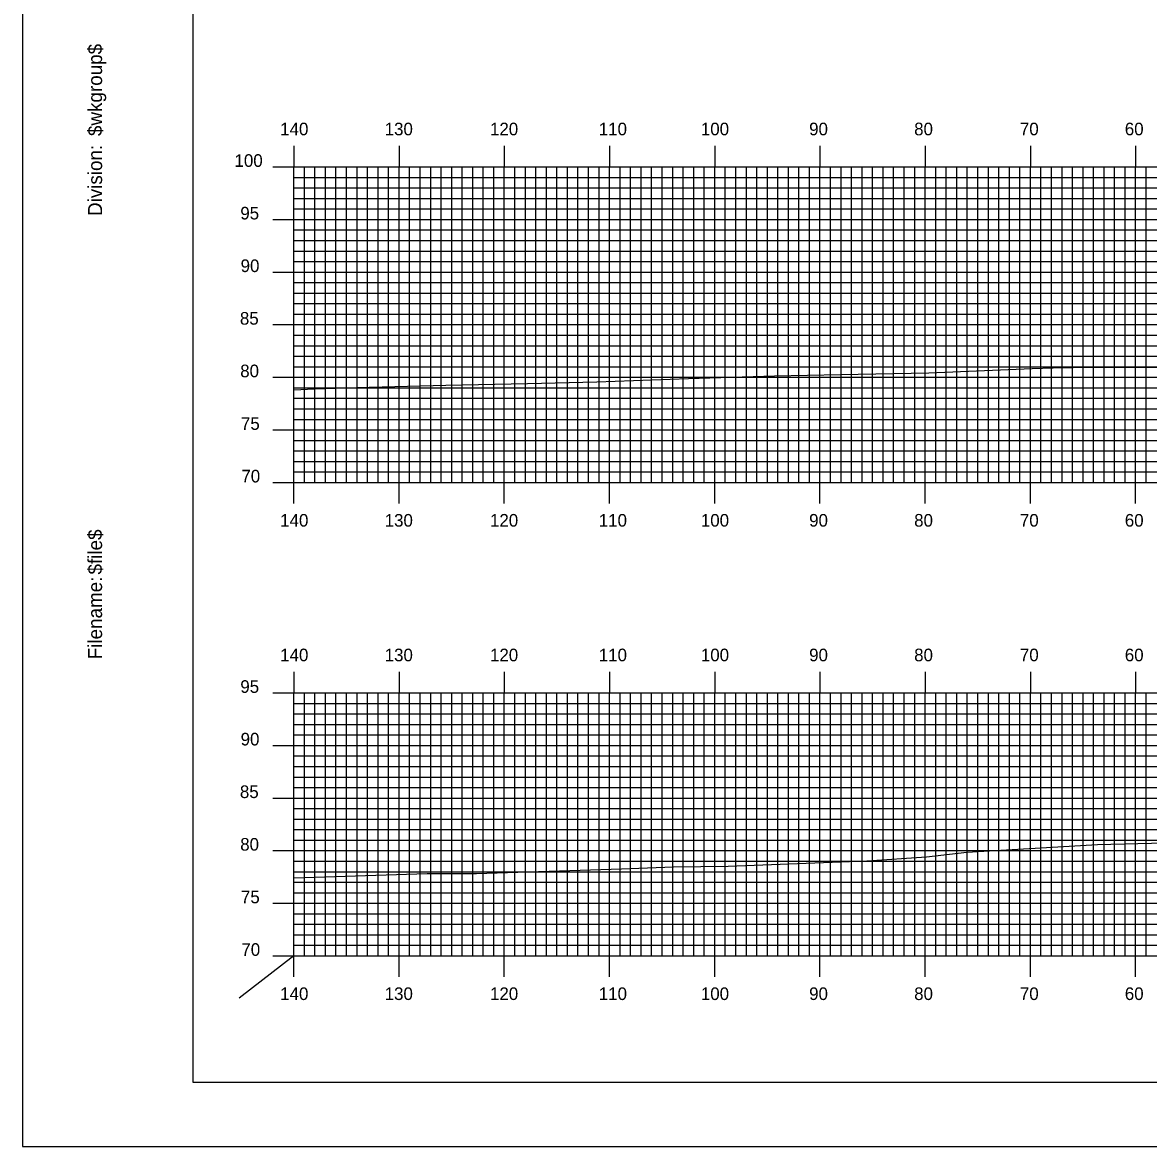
# Model space of a CAD drawing. Extents: x 1777531 to 1777875, y 442591 to 442811.
# Drawn here: x 1777531.5 to 1777638.5, y 442590.5 to 442697.4 of the extents above; entities that cross this region are included whole.
import ezdxf

# ---------------------------------------------------------------- set-up
doc = ezdxf.new("R2010")
doc.units = 0
for name, color, linetype in [('BORDER', 7, 'Continuous'), ('H_V ANNOTATION', 7, 'Continuous'), ('MAJOR', 7, 'Continuous'), ('MINOR', 7, 'Continuous'), ('PLOT BOUNDARY', 7, 'Continuous'), ('S_Roadway_Centerline', 7, 'Continuous')]:
    doc.layers.add(name, color=color, linetype=linetype)

msp = doc.modelspace()

# ---------------------------------------------------------------- linework, layer by layer
at = {"layer": 'BORDER'}
msp.add_lwpolyline([(1777547.68, 442596.67), (1777867.68, 442596.67), (1777867.68, 442806.67), (1777547.68, 442806.67)], close=True, dxfattribs=at)
at = {"layer": 'MAJOR'}
for p, q in [((1777557.28, 442685.67), (1777557.28, 442683.67)), ((1777567.28, 442685.67), (1777567.28, 442683.67)), ((1777577.28, 442685.67), (1777577.28, 442683.67)), ((1777587.28, 442685.67), (1777587.28, 442683.67)), ((1777597.28, 442685.67), (1777597.28, 442683.67)), ((1777607.28, 442685.67), (1777607.28, 442683.67)), ((1777617.28, 442685.67), (1777617.28, 442683.67)), ((1777627.28, 442685.67), (1777627.28, 442683.67)), ((1777637.28, 442685.67), (1777637.28, 442683.67)), ((1777555.27, 442683.67), (1777557.28, 442683.67)), ((1777557.28, 442683.67), (1777837.28, 442683.67)), ((1777557.28, 442653.67), (1777557.28, 442683.67)), ((1777557.28, 442653.67), (1777557.28, 442683.67)), ((1777557.28, 442683.67), (1777837.28, 442683.67)), ((1777567.28, 442653.67), (1777567.28, 442683.67)), ((1777577.28, 442653.67), (1777577.28, 442683.67)), ((1777587.28, 442653.67), (1777587.28, 442683.67)), ((1777597.28, 442653.67), (1777597.28, 442683.67)), ((1777607.28, 442653.67), (1777607.28, 442683.67)), ((1777617.28, 442653.67), (1777617.28, 442683.67)), ((1777627.28, 442653.67), (1777627.28, 442683.67)), ((1777637.28, 442653.67), (1777637.28, 442683.67)), ((1777555.27, 442678.67), (1777557.28, 442678.67)), ((1777557.28, 442678.67), (1777837.28, 442678.67)), ((1777555.27, 442673.67), (1777557.28, 442673.67)), ((1777557.28, 442673.67), (1777837.28, 442673.67)), ((1777555.27, 442668.67), (1777557.28, 442668.67)), ((1777557.28, 442668.67), (1777837.28, 442668.67)), ((1777555.27, 442663.67), (1777557.28, 442663.67)), ((1777557.28, 442663.67), (1777837.28, 442663.67)), ((1777555.27, 442658.67), (1777557.28, 442658.67)), ((1777557.28, 442658.67), (1777837.28, 442658.67)), ((1777555.27, 442653.67), (1777557.28, 442653.67)), ((1777557.28, 442653.67), (1777837.28, 442653.67)), ((1777557.28, 442653.67), (1777837.28, 442653.67)), ((1777557.28, 442651.66), (1777557.28, 442653.67)), ((1777567.28, 442651.66), (1777567.28, 442653.67)), ((1777577.28, 442651.66), (1777577.28, 442653.67)), ((1777587.28, 442651.66), (1777587.28, 442653.67)), ((1777597.28, 442651.66), (1777597.28, 442653.67)), ((1777607.28, 442651.66), (1777607.28, 442653.67)), ((1777617.28, 442651.66), (1777617.28, 442653.67)), ((1777627.28, 442651.66), (1777627.28, 442653.67)), ((1777637.28, 442651.66), (1777637.28, 442653.67)), ((1777557.28, 442635.67), (1777557.28, 442633.67)), ((1777567.28, 442635.67), (1777567.28, 442633.67)), ((1777577.28, 442635.67), (1777577.28, 442633.67)), ((1777587.28, 442635.67), (1777587.28, 442633.67)), ((1777597.28, 442635.67), (1777597.28, 442633.67)), ((1777607.28, 442635.67), (1777607.28, 442633.67)), ((1777617.28, 442635.67), (1777617.28, 442633.67)), ((1777627.28, 442635.67), (1777627.28, 442633.67)), ((1777637.28, 442635.67), (1777637.28, 442633.67)), ((1777555.27, 442633.67), (1777557.28, 442633.67)), ((1777557.28, 442633.67), (1777837.28, 442633.67)), ((1777557.28, 442608.67), (1777557.28, 442633.67)), ((1777557.28, 442608.67), (1777557.28, 442633.67)), ((1777557.28, 442633.67), (1777837.28, 442633.67)), ((1777567.28, 442608.67), (1777567.28, 442633.67)), ((1777577.28, 442608.67), (1777577.28, 442633.67)), ((1777587.28, 442608.67), (1777587.28, 442633.67)), ((1777597.28, 442608.67), (1777597.28, 442633.67)), ((1777607.28, 442608.67), (1777607.28, 442633.67)), ((1777617.28, 442608.67), (1777617.28, 442633.67)), ((1777627.28, 442608.67), (1777627.28, 442633.67)), ((1777637.28, 442608.67), (1777637.28, 442633.67)), ((1777555.27, 442628.67), (1777557.28, 442628.67)), ((1777557.28, 442628.67), (1777837.28, 442628.67)), ((1777555.27, 442623.67), (1777557.28, 442623.67)), ((1777557.28, 442623.67), (1777837.28, 442623.67)), ((1777555.27, 442618.67), (1777557.28, 442618.67)), ((1777557.28, 442618.67), (1777837.28, 442618.67)), ((1777555.27, 442613.67), (1777557.28, 442613.67)), ((1777557.28, 442613.67), (1777837.28, 442613.67)), ((1777557.28, 442608.67), (1777552.09, 442604.64)), ((1777555.27, 442608.67), (1777557.28, 442608.67)), ((1777557.28, 442608.67), (1777837.28, 442608.67)), ((1777557.28, 442608.67), (1777837.28, 442608.67)), ((1777557.28, 442606.66), (1777557.28, 442608.67)), ((1777567.28, 442606.66), (1777567.28, 442608.67)), ((1777577.28, 442606.66), (1777577.28, 442608.67)), ((1777587.28, 442606.66), (1777587.28, 442608.67)), ((1777597.28, 442606.66), (1777597.28, 442608.67)), ((1777607.28, 442606.66), (1777607.28, 442608.67)), ((1777617.28, 442606.66), (1777617.28, 442608.67)), ((1777627.28, 442606.66), (1777627.28, 442608.67)), ((1777637.28, 442606.66), (1777637.28, 442608.67))]:
    msp.add_line(p, q, dxfattribs=at)
at = {"layer": 'MINOR'}
for p, q in [((1777558.28, 442653.67), (1777558.28, 442683.67)), ((1777559.28, 442653.67), (1777559.28, 442683.67)), ((1777560.28, 442653.67), (1777560.28, 442683.67)), ((1777561.28, 442653.67), (1777561.28, 442683.67)), ((1777562.28, 442653.67), (1777562.28, 442683.67)), ((1777563.28, 442653.67), (1777563.28, 442683.67)), ((1777564.28, 442653.67), (1777564.28, 442683.67)), ((1777565.28, 442653.67), (1777565.28, 442683.67)), ((1777566.28, 442653.67), (1777566.28, 442683.67)), ((1777568.28, 442653.67), (1777568.28, 442683.67)), ((1777569.28, 442653.67), (1777569.28, 442683.67)), ((1777570.28, 442653.67), (1777570.28, 442683.67)), ((1777571.28, 442653.67), (1777571.28, 442683.67)), ((1777572.28, 442653.67), (1777572.28, 442683.67)), ((1777573.28, 442653.67), (1777573.28, 442683.67)), ((1777574.28, 442653.67), (1777574.28, 442683.67)), ((1777575.28, 442653.67), (1777575.28, 442683.67)), ((1777576.28, 442653.67), (1777576.28, 442683.67)), ((1777578.28, 442653.67), (1777578.28, 442683.67)), ((1777579.28, 442653.67), (1777579.28, 442683.67)), ((1777580.28, 442653.67), (1777580.28, 442683.67)), ((1777581.28, 442653.67), (1777581.28, 442683.67)), ((1777582.28, 442653.67), (1777582.28, 442683.67)), ((1777583.28, 442653.67), (1777583.28, 442683.67)), ((1777584.28, 442653.67), (1777584.28, 442683.67)), ((1777585.28, 442653.67), (1777585.28, 442683.67)), ((1777586.28, 442653.67), (1777586.28, 442683.67)), ((1777588.28, 442653.67), (1777588.28, 442683.67)), ((1777589.28, 442653.67), (1777589.28, 442683.67)), ((1777590.28, 442653.67), (1777590.28, 442683.67)), ((1777591.28, 442653.67), (1777591.28, 442683.67)), ((1777592.28, 442653.67), (1777592.28, 442683.67)), ((1777593.28, 442653.67), (1777593.28, 442683.67)), ((1777594.28, 442653.67), (1777594.28, 442683.67)), ((1777595.28, 442653.67), (1777595.28, 442683.67)), ((1777596.28, 442653.67), (1777596.28, 442683.67)), ((1777598.28, 442653.67), (1777598.28, 442683.67)), ((1777599.28, 442653.67), (1777599.28, 442683.67)), ((1777600.28, 442653.67), (1777600.28, 442683.67)), ((1777601.28, 442653.67), (1777601.28, 442683.67)), ((1777602.28, 442653.67), (1777602.28, 442683.67)), ((1777603.28, 442653.67), (1777603.28, 442683.67)), ((1777604.28, 442653.67), (1777604.28, 442683.67)), ((1777605.28, 442653.67), (1777605.28, 442683.67)), ((1777606.28, 442653.67), (1777606.28, 442683.67)), ((1777608.28, 442653.67), (1777608.28, 442683.67)), ((1777609.28, 442653.67), (1777609.28, 442683.67)), ((1777610.28, 442653.67), (1777610.28, 442683.67)), ((1777611.28, 442653.67), (1777611.28, 442683.67)), ((1777612.28, 442653.67), (1777612.28, 442683.67)), ((1777613.28, 442653.67), (1777613.28, 442683.67)), ((1777614.28, 442653.67), (1777614.28, 442683.67)), ((1777615.28, 442653.67), (1777615.28, 442683.67)), ((1777616.28, 442653.67), (1777616.28, 442683.67)), ((1777618.28, 442653.67), (1777618.28, 442683.67)), ((1777619.28, 442653.67), (1777619.28, 442683.67)), ((1777620.28, 442653.67), (1777620.28, 442683.67)), ((1777621.28, 442653.67), (1777621.28, 442683.67)), ((1777622.28, 442653.67), (1777622.28, 442683.67)), ((1777623.28, 442653.67), (1777623.28, 442683.67)), ((1777624.28, 442653.67), (1777624.28, 442683.67)), ((1777625.28, 442653.67), (1777625.28, 442683.67)), ((1777626.28, 442653.67), (1777626.28, 442683.67)), ((1777628.28, 442653.67), (1777628.28, 442683.67)), ((1777629.28, 442653.67), (1777629.28, 442683.67)), ((1777630.28, 442653.67), (1777630.28, 442683.67)), ((1777631.28, 442653.67), (1777631.28, 442683.67)), ((1777632.28, 442653.67), (1777632.28, 442683.67)), ((1777633.28, 442653.67), (1777633.28, 442683.67)), ((1777634.28, 442653.67), (1777634.28, 442683.67)), ((1777635.28, 442653.67), (1777635.28, 442683.67)), ((1777636.28, 442653.67), (1777636.28, 442683.67)), ((1777638.28, 442653.67), (1777638.28, 442683.67)), ((1777557.28, 442682.67), (1777837.28, 442682.67)), ((1777557.28, 442682.67), (1777559.28, 442682.67)), ((1777557.28, 442681.67), (1777837.28, 442681.67)), ((1777557.28, 442681.67), (1777559.28, 442681.67)), ((1777557.28, 442680.67), (1777837.28, 442680.67)), ((1777557.28, 442680.67), (1777559.28, 442680.67)), ((1777557.28, 442679.67), (1777837.28, 442679.67)), ((1777557.28, 442679.67), (1777559.28, 442679.67)), ((1777557.28, 442677.67), (1777837.28, 442677.67)), ((1777557.28, 442677.67), (1777559.28, 442677.67)), ((1777557.28, 442676.67), (1777837.28, 442676.67)), ((1777557.28, 442676.67), (1777559.28, 442676.67)), ((1777557.28, 442675.67), (1777837.28, 442675.67)), ((1777557.28, 442675.67), (1777559.28, 442675.67)), ((1777557.28, 442674.67), (1777837.28, 442674.67)), ((1777557.28, 442674.67), (1777559.28, 442674.67)), ((1777557.28, 442672.67), (1777837.28, 442672.67)), ((1777557.28, 442672.67), (1777559.28, 442672.67)), ((1777557.28, 442671.67), (1777837.28, 442671.67)), ((1777557.28, 442671.67), (1777559.28, 442671.67)), ((1777557.28, 442670.67), (1777837.28, 442670.67)), ((1777557.28, 442670.67), (1777559.28, 442670.67)), ((1777557.28, 442669.67), (1777837.28, 442669.67)), ((1777557.28, 442669.67), (1777559.28, 442669.67)), ((1777557.28, 442667.67), (1777837.28, 442667.67)), ((1777557.28, 442667.67), (1777559.28, 442667.67)), ((1777557.28, 442666.67), (1777837.28, 442666.67)), ((1777557.28, 442666.67), (1777559.28, 442666.67)), ((1777557.28, 442665.67), (1777837.28, 442665.67)), ((1777557.28, 442665.67), (1777559.28, 442665.67)), ((1777557.28, 442664.67), (1777837.28, 442664.67)), ((1777557.28, 442664.67), (1777559.28, 442664.67)), ((1777557.28, 442662.67), (1777837.28, 442662.67)), ((1777557.28, 442662.67), (1777559.28, 442662.67)), ((1777557.28, 442661.67), (1777837.28, 442661.67)), ((1777557.28, 442661.67), (1777559.28, 442661.67)), ((1777557.28, 442660.67), (1777837.28, 442660.67)), ((1777557.28, 442660.67), (1777559.28, 442660.67)), ((1777557.28, 442659.67), (1777837.28, 442659.67)), ((1777557.28, 442659.67), (1777559.28, 442659.67)), ((1777557.28, 442657.67), (1777837.28, 442657.67)), ((1777557.28, 442657.67), (1777559.28, 442657.67)), ((1777557.28, 442656.67), (1777837.28, 442656.67)), ((1777557.28, 442656.67), (1777559.28, 442656.67)), ((1777557.28, 442655.67), (1777837.28, 442655.67)), ((1777557.28, 442655.67), (1777559.28, 442655.67)), ((1777557.28, 442654.67), (1777837.28, 442654.67)), ((1777557.28, 442654.67), (1777559.28, 442654.67)), ((1777558.28, 442608.67), (1777558.28, 442633.67)), ((1777559.28, 442608.67), (1777559.28, 442633.67)), ((1777560.28, 442608.67), (1777560.28, 442633.67)), ((1777561.28, 442608.67), (1777561.28, 442633.67)), ((1777562.28, 442608.67), (1777562.28, 442633.67)), ((1777563.28, 442608.67), (1777563.28, 442633.67)), ((1777564.28, 442608.67), (1777564.28, 442633.67)), ((1777565.28, 442608.67), (1777565.28, 442633.67)), ((1777566.28, 442608.67), (1777566.28, 442633.67)), ((1777568.28, 442608.67), (1777568.28, 442633.67)), ((1777569.28, 442608.67), (1777569.28, 442633.67)), ((1777570.28, 442608.67), (1777570.28, 442633.67)), ((1777571.28, 442608.67), (1777571.28, 442633.67)), ((1777572.28, 442608.67), (1777572.28, 442633.67)), ((1777573.28, 442608.67), (1777573.28, 442633.67)), ((1777574.28, 442608.67), (1777574.28, 442633.67)), ((1777575.28, 442608.67), (1777575.28, 442633.67)), ((1777576.28, 442608.67), (1777576.28, 442633.67)), ((1777578.28, 442608.67), (1777578.28, 442633.67)), ((1777579.28, 442608.67), (1777579.28, 442633.67)), ((1777580.28, 442608.67), (1777580.28, 442633.67)), ((1777581.28, 442608.67), (1777581.28, 442633.67)), ((1777582.28, 442608.67), (1777582.28, 442633.67)), ((1777583.28, 442608.67), (1777583.28, 442633.67)), ((1777584.28, 442608.67), (1777584.28, 442633.67)), ((1777585.28, 442608.67), (1777585.28, 442633.67)), ((1777586.28, 442608.67), (1777586.28, 442633.67)), ((1777588.28, 442608.67), (1777588.28, 442633.67)), ((1777589.28, 442608.67), (1777589.28, 442633.67)), ((1777590.28, 442608.67), (1777590.28, 442633.67)), ((1777591.28, 442608.67), (1777591.28, 442633.67)), ((1777592.28, 442608.67), (1777592.28, 442633.67)), ((1777593.28, 442608.67), (1777593.28, 442633.67)), ((1777594.28, 442608.67), (1777594.28, 442633.67)), ((1777595.28, 442608.67), (1777595.28, 442633.67)), ((1777596.28, 442608.67), (1777596.28, 442633.67)), ((1777598.28, 442608.67), (1777598.28, 442633.67)), ((1777599.28, 442608.67), (1777599.28, 442633.67)), ((1777600.28, 442608.67), (1777600.28, 442633.67)), ((1777601.28, 442608.67), (1777601.28, 442633.67)), ((1777602.28, 442608.67), (1777602.28, 442633.67)), ((1777603.28, 442608.67), (1777603.28, 442633.67)), ((1777604.28, 442608.67), (1777604.28, 442633.67)), ((1777605.28, 442608.67), (1777605.28, 442633.67)), ((1777606.28, 442608.67), (1777606.28, 442633.67)), ((1777608.28, 442608.67), (1777608.28, 442633.67)), ((1777609.28, 442608.67), (1777609.28, 442633.67)), ((1777610.28, 442608.67), (1777610.28, 442633.67)), ((1777611.28, 442608.67), (1777611.28, 442633.67)), ((1777612.28, 442608.67), (1777612.28, 442633.67)), ((1777613.28, 442608.67), (1777613.28, 442633.67)), ((1777614.28, 442608.67), (1777614.28, 442633.67)), ((1777615.28, 442608.67), (1777615.28, 442633.67)), ((1777616.28, 442608.67), (1777616.28, 442633.67)), ((1777618.28, 442608.67), (1777618.28, 442633.67)), ((1777619.28, 442608.67), (1777619.28, 442633.67)), ((1777620.28, 442608.67), (1777620.28, 442633.67)), ((1777621.28, 442608.67), (1777621.28, 442633.67)), ((1777622.28, 442608.67), (1777622.28, 442633.67)), ((1777623.28, 442608.67), (1777623.28, 442633.67)), ((1777624.28, 442608.67), (1777624.28, 442633.67)), ((1777625.28, 442608.67), (1777625.28, 442633.67)), ((1777626.28, 442608.67), (1777626.28, 442633.67)), ((1777628.28, 442608.67), (1777628.28, 442633.67)), ((1777629.28, 442608.67), (1777629.28, 442633.67)), ((1777630.28, 442608.67), (1777630.28, 442633.67)), ((1777631.28, 442608.67), (1777631.28, 442633.67)), ((1777632.28, 442608.67), (1777632.28, 442633.67)), ((1777633.28, 442608.67), (1777633.28, 442633.67)), ((1777634.28, 442608.67), (1777634.28, 442633.67)), ((1777635.28, 442608.67), (1777635.28, 442633.67)), ((1777636.28, 442608.67), (1777636.28, 442633.67)), ((1777638.28, 442608.67), (1777638.28, 442633.67)), ((1777557.28, 442632.67), (1777837.28, 442632.67)), ((1777557.28, 442632.67), (1777559.28, 442632.67)), ((1777557.28, 442631.67), (1777837.28, 442631.67)), ((1777557.28, 442631.67), (1777559.28, 442631.67)), ((1777557.28, 442630.67), (1777837.28, 442630.67)), ((1777557.28, 442630.67), (1777559.28, 442630.67)), ((1777557.28, 442629.67), (1777837.28, 442629.67)), ((1777557.28, 442629.67), (1777559.28, 442629.67)), ((1777557.28, 442627.67), (1777837.28, 442627.67)), ((1777557.28, 442627.67), (1777559.28, 442627.67)), ((1777557.28, 442626.67), (1777837.28, 442626.67)), ((1777557.28, 442626.67), (1777559.28, 442626.67)), ((1777557.28, 442625.67), (1777837.28, 442625.67)), ((1777557.28, 442625.67), (1777559.28, 442625.67)), ((1777557.28, 442624.67), (1777837.28, 442624.67)), ((1777557.28, 442624.67), (1777559.28, 442624.67)), ((1777557.28, 442622.67), (1777837.28, 442622.67)), ((1777557.28, 442622.67), (1777559.28, 442622.67)), ((1777557.28, 442621.67), (1777837.28, 442621.67)), ((1777557.28, 442621.67), (1777559.28, 442621.67)), ((1777557.28, 442620.67), (1777837.28, 442620.67)), ((1777557.28, 442620.67), (1777559.28, 442620.67)), ((1777557.28, 442619.67), (1777837.28, 442619.67)), ((1777557.28, 442619.67), (1777559.28, 442619.67)), ((1777557.28, 442617.67), (1777837.28, 442617.67)), ((1777557.28, 442617.67), (1777559.28, 442617.67)), ((1777557.28, 442616.67), (1777837.28, 442616.67)), ((1777557.28, 442616.67), (1777559.28, 442616.67)), ((1777557.28, 442615.67), (1777837.28, 442615.67)), ((1777557.28, 442615.67), (1777559.28, 442615.67)), ((1777557.28, 442614.67), (1777837.28, 442614.67)), ((1777557.28, 442614.67), (1777559.28, 442614.67)), ((1777557.28, 442612.67), (1777837.28, 442612.67)), ((1777557.28, 442612.67), (1777559.28, 442612.67)), ((1777557.28, 442611.67), (1777837.28, 442611.67)), ((1777557.28, 442611.67), (1777559.28, 442611.67)), ((1777557.28, 442610.67), (1777837.28, 442610.67)), ((1777557.28, 442610.67), (1777559.28, 442610.67)), ((1777557.28, 442609.67), (1777837.28, 442609.67)), ((1777557.28, 442609.67), (1777559.28, 442609.67))]:
    msp.add_line(p, q, dxfattribs=at)
at = {"layer": 'PLOT BOUNDARY'}
msp.add_lwpolyline([(1777531.49, 442590.55), (1777871.49, 442590.55), (1777871.49, 442810.55), (1777531.49, 442810.55)], close=True, dxfattribs=at)
at = {"layer": 'S_Roadway_Centerline'}
for points in [[(1777557.28, 442662.47), (1777559.25, 442662.57), (1777563.24, 442662.7), (1777571.71, 442662.93), (1777579.49, 442663.07), (1777586.07, 442663.23), (1777594.77, 442663.56), (1777602.97, 442663.81), (1777609.22, 442663.94), (1777617.62, 442664.08), (1777627.43, 442664.5), (1777629.43, 442664.56), (1777631.33, 442664.6), (1777640.64, 442664.63)], [(1777557.28, 442616.08), (1777569.96, 442616.51), (1777574.64, 442616.49), (1777588.4, 442616.94), (1777593.35, 442617.14), (1777598.54, 442617.21), (1777611.73, 442617.7), (1777617.39, 442618.07), (1777621.22, 442618.53), (1777633.64, 442619.26), (1777646.46, 442619.57)]]:
    msp.add_lwpolyline(points, dxfattribs=at)

# ---------------------------------------------------------------- texts
at = {"layer": 'BORDER'}
for s, p in [('$wkgroup$', (1777539.05, 442686.6)), ('Division:', (1777539.05, 442679)), ('$file$', (1777539.05, 442644.92)), ('Filename:', (1777539.05, 442636.86))]:
    msp.add_text(s, height=1.339, rotation=90, dxfattribs=at).set_placement(p)
at = {"layer": 'H_V ANNOTATION'}
for s, p in [('140', (1777555.98, 442686.67)), ('130', (1777565.91, 442686.67)), ('120', (1777575.92, 442686.67)), ('110', (1777586.26, 442686.67)), ('100', (1777595.96, 442686.67)), ('90', (1777606.25, 442686.67)), ('80', (1777616.23, 442686.67)), ('70', (1777626.28, 442686.67)), ('60', (1777636.25, 442686.67)), ('100', (1777551.64, 442683.67)), ('95', (1777552.19, 442678.67)), ('90', (1777552.22, 442673.67)), ('85', (1777552.15, 442668.67)), ('80', (1777552.18, 442663.67)), ('75', (1777552.25, 442658.67)), ('70', (1777552.29, 442653.67)), ('140', (1777555.98, 442649.47)), ('130', (1777565.91, 442649.47)), ('120', (1777575.92, 442649.47)), ('110', (1777586.26, 442649.47)), ('100', (1777595.96, 442649.47)), ('90', (1777606.25, 442649.47)), ('80', (1777616.23, 442649.47)), ('70', (1777626.28, 442649.47)), ('60', (1777636.25, 442649.47)), ('140', (1777555.98, 442636.67)), ('130', (1777565.91, 442636.67)), ('120', (1777575.92, 442636.67)), ('110', (1777586.26, 442636.67)), ('100', (1777595.96, 442636.67)), ('90', (1777606.25, 442636.67)), ('80', (1777616.23, 442636.67)), ('70', (1777626.28, 442636.67)), ('60', (1777636.25, 442636.67)), ('95', (1777552.19, 442633.67)), ('90', (1777552.22, 442628.67)), ('85', (1777552.15, 442623.67)), ('80', (1777552.18, 442618.67)), ('75', (1777552.25, 442613.67)), ('70', (1777552.29, 442608.67)), ('140', (1777555.98, 442604.47)), ('130', (1777565.91, 442604.47)), ('120', (1777575.92, 442604.47)), ('110', (1777586.26, 442604.47)), ('100', (1777595.96, 442604.47)), ('90', (1777606.25, 442604.47)), ('80', (1777616.23, 442604.47)), ('70', (1777626.28, 442604.47)), ('60', (1777636.25, 442604.47))]:
    msp.add_text(s, height=1.2, dxfattribs=at).set_placement(p)
at = {"layer": 'MAJOR'}
for p in [(1777557.27, 442653.67), (1777557.27, 442608.67)]:
    msp.add_text('-', height=0.012, dxfattribs=at).set_placement(p)

doc.saveas('drawing.dxf')
